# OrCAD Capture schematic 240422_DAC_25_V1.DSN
size A4; title: DA CONVERTOR; rev: 1.0; note: 2024.04.22
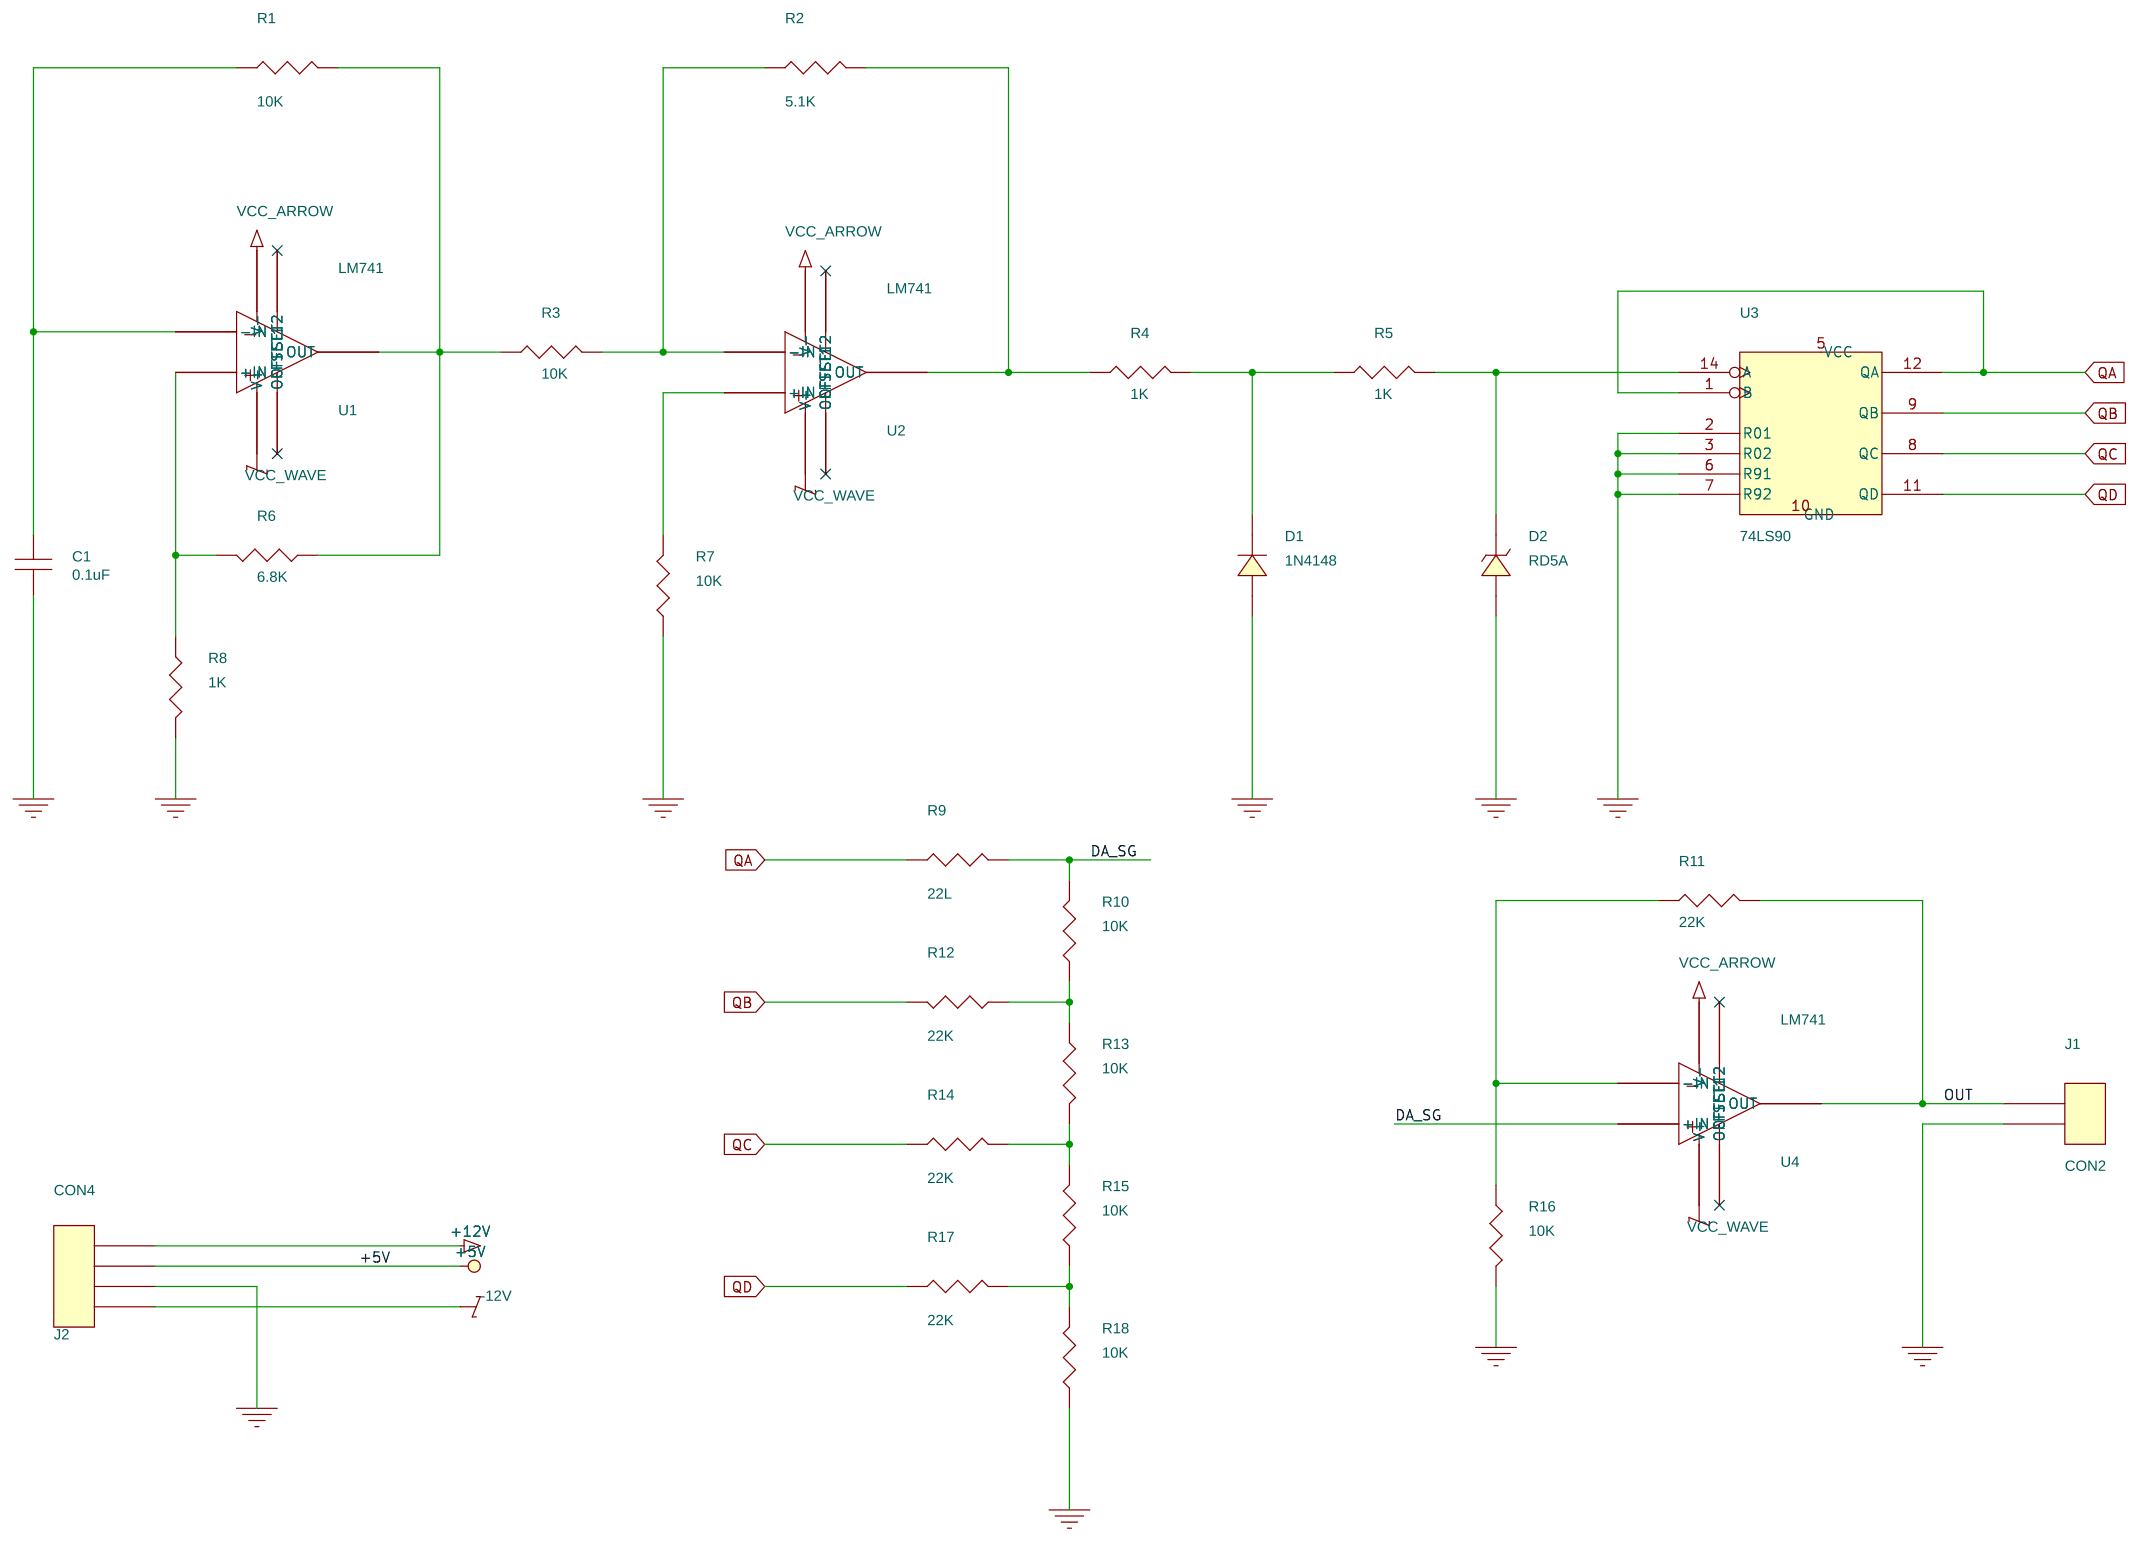
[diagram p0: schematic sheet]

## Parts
C1  0.1uF  [CAPCK05]
D1  1N4148  [DO41]
D2  RD5A  [DO41]
J1  CON2  [JUMPER2]
J2  CON4  [JUMPER4]
R1  10K  [RES400]
R2  5.1K  [RES400]
R3  10K  [RES400]
R4  1K  [RES400]
R5  1K  [RES400]
R6  6.8K  [RES400]
R7  10K  [RES400]
R8  1K  [RES400]
R9  22L  [RES400]
R10  10K  [RES400]
R11  22K  [RES400]
R12  22K  [RES400]
R13  10K  [RES400]
R14  22K  [RES400]
R15  10K  [RES400]
R16  10K  [RES400]
R17  22K  [RES400]
R18  10K  [RES400]
U1  LM741  [DIP8_3]
U2  LM741  [DIP8_3]
U3  74LS90  [DIP14_3]
U4  LM741  [DIP8_3]

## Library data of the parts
C1 = CAP_NP
D1 = DIODE
D2 = DIODE_ZENER
J1 = CON2
J2 = CON4
R1-R18 = R
U1 = LM741_1: NC: 8
U2 U4 = LM741_2: NC: 8
U3 = 74LS90_1: NC: 4, 13

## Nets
+12V: J2.1 U1.4(V-) U2.4(V-) U4.4(V-)
-12V: J2.4 U1.7(V+) U2.7(V+) U4.7(V+)
GND: C1.2 D1.2(A) D2.2(ANODE) J1.2 J2.3 R7.1 R8.2 R16.2 R18.1 U3.2(R01) U3.3(R02) U3.6(R91) U3.7(R92) U3.10(GND)
VCC: J2.2 U3.5(VCC)
DA_SG: R9.2 R10.2 U4.3(+IN)
OUT: J1.1 R11.2 U4.6(OUT)
QA: R9.1 U3.1(B) U3.12(QA)
QB: R12.2 U3.9(QB)
QC: R14.1 U3.8(QC)
QD: R17.1 U3.11(QD)
N01760: R1.2 R3.1 R6.1 U1.6(OUT)
N01790: C1.1 R1.1 U1.2(-IN)
N01808: R6.2 R8.1 U1.3(+IN)
N01860: R2.1 R3.2 U2.2(-IN)
N01877: R2.2 R4.1 U2.6(OUT)
N01881: D1.1(K) R4.2 R5.1
N01913: D2.1(CATHODE) R5.2 U3.14(A)
N02059: R11.1 R16.1 U4.2(-IN)
N02108: R7.2 U2.3(+IN)
N02187: R10.1 R12.1 R13.1
N02201: R13.2 R14.2 R15.2
N02215: R15.1 R17.2 R18.2

Not connected (* = marked no-connect by the designer): U1 1(OFFSET1)* 5(OFFSET2)*; U2 1(OFFSET1)* 5(OFFSET2)*; U4 1(OFFSET1)* 5(OFFSET2)*
